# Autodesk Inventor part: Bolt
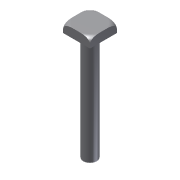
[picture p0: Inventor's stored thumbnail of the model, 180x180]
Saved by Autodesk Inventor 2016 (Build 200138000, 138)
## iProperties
Created: 2009-04
Part Number: Bolt
Document SubType Name: Modeling
Designer: Sham
Density: 1 g/cm^3
Material: Generic
Mass: 15.4123 g
Surface Area: 54.8695 cm^2
Volume: 15.4123 cm^3
Appearance: Default
Author: Sham
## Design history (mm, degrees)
sketch "Sketch1"
  geometry: L1 (-12, 12)-(12, 12); L2 (12, 12)-(12, -12); L3 (12, -12)-(-12, -12); L4 (-12, -12)-(-12, 12); 1 further point
  constraints: 8 end point, 2 parallel, 2 perpendicular, 1 horizontal, 1 other
  dimensions: "d0" = 24 distance of L1.start L1.end; "d1" = 12 distance from line of L2 point (0, 0); "d2" = 12 distance from line of L1 point (0, 0)
extrude "Extrusion1" new body sketch "Sketch1" distance "d3" = 8; taper "d4" = 0 deg
sketch "Sketch2"
  geometry: C1 r 6 at (0, 0)
  constraints: 1 centre point
  dimensions: "d5" = 12 diameter of C1
extrude "Extrusion2" join sketch "Sketch2" distance "d6" = 96; taper "d7" = 0 deg
workpoint "Work Point1"
workplane "Work Plane1"
sketch "Sketch3"
  geometry: L1 (33.941, 5)-(33.941, 6); L2 (28.941, 0)-(28.405, 0); L3 (16.971, 125.007)-(16.971, -22.043) reference; A1 r 5 centre (28.941, 5) between (28.941, 0) and (33.941, 5); 1 further point
  constraints: 4 end point, 2 point on circle, 2 point on line, 2 tangent, 1 centre point, 1 perpendicular
  dimensions: "d10" = 5 radius of A1
revolve "Revolution1" sketch "Sketch3" stored, may be unused: angle "d12" = 90 deg
body "Solid1"
other parameters: "d11" = 90 deg
